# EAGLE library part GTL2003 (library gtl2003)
8-bit bidirectional low voltage translator
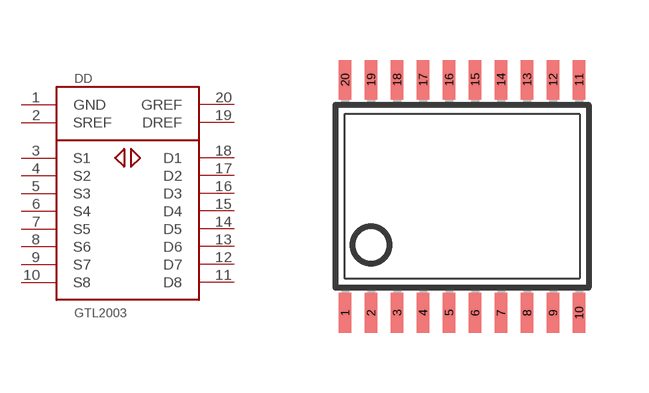
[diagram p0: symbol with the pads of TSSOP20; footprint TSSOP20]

Designator prefix DD

## GTL2003PW  [TSSOP20]
1  GND  pwr
2  SREF  in
3  S1
4  S2
5  S3
6  S4
7  S5
8  S6
9  S7
10  S8
11  D8
12  D7
13  D6
14  D5
15  D4
16  D3
17  D2
18  D1
19  DREF  in
20  GREF  in

## Footprint TSSOP20 (pad centres in mm)
Thin Shrink Small Outline Plastic 20 MAX3223-MAX3243.pdf
smd 0.305 x 0.991: 1 -2.925,-2.918; 2 -2.275,-2.918; 3 -1.625,-2.918; 4 -0.975,-2.918; 5 -0.325,-2.918; 6 0.325,-2.918; 7 0.975,-2.918; 8 1.625,-2.918; 9 2.275,-2.918; 10 2.925,-2.918; 11 2.925,2.918; 12 2.275,2.918; 13 1.625,2.918; 14 0.975,2.918; 15 0.325,2.918; 16 -0.325,2.918; 17 -0.975,2.918; 18 -1.625,2.918; 19 -2.275,2.918; 20 -2.925,2.918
